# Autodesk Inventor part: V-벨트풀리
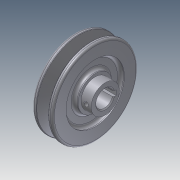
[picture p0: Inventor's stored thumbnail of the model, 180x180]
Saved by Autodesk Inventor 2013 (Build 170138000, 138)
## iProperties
Company: 한국ATC센터
Created: 2014-07
Part Number: V-벨트풀리
Document SubType Name: Modeling
Designer: KYOUNG IL JANG
Density: 7.86 g/cm^3
Material: 강, 연강
Mass: 593.01 g
Surface Area: 234.121 cm^2
Volume: 75.4466 cm^3
Author: KYOUNG IL JANG
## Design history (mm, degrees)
sketch "스케치1"
  geometry: L1 (-15, 0)-(15, 0); L2 (-15, 0)-(-15, 17); L3 (-15, 17)-(-11, 17); L4 (-11, 17)-(-11, 29); L5 (-11, 29)-(-15, 29); L6 (-15, 29)-(-15, 42.5); L7 (-15, 42.5)-(-10.976, 42.5); L8 (-10.976, 42.5)-(-7.154, 30); L9 (-7.154, 30)-(-2.846, 30); L10 (-2.846, 30)-(0.976, 42.5); L11 (0.976, 42.5)-(5, 42.5); L12 (5, 42.5)-(5, 29); L13 (5, 29)-(1, 29); L14 (1, 29)-(1, 17); L15 (1, 17)-(5, 17); L16 (5, 17)-(5, 14); L17 (5, 14)-(15, 14); L18 (15, 14)-(15, 0); L19 (-9.6, 38)-(-0.4, 38); 2 further points
  constraints: 38 end point, 11 parallel, 7 collinear, 3 equal length, 3 perpendicular, 2 point on line, 1 coincident, 1 horizontal, 1 midpoint
  dimensions: "d0" = 30 distance of L1.start L1.end; "d1" = 4.5 distance between parallel lines of L7 L19; "d2" = 8 distance between parallel lines of L9 L19; "d3" = 9.2 distance of L19.start L19.end; "d4" = 34 deg angle of L10 L8; "d5" = 20 distance between parallel lines of L12 L6; "d6" = 76 diameter of L19 L1; "d7" = 4 distance of L2.end L3.end; "d8" = 34 diameter of L3 L1; "d9" = 58 diameter of L5 L1; "d10" = 28 diameter of L17 L1
revolve "회전1" sketch "스케치1" stored, may be unused: angle "d11" = 90 deg
sketch "스케치2"
  geometry: L1 (-2.5, 8.124)-(-2.5, 10.8); L2 (-2.5, 10.8)-(2.5, 10.8); L3 (2.5, 10.8)-(2.5, 8.124); A1 r 8.5 centre (0, 0) between (-2.5, 8.124) and (2.5, 8.124); 1 further point
  constraints: 6 end point, 2 parallel, 2 point on circle, 1 centre point, 1 coincident, 1 horizontal, 1 vertical
  dimensions: "d12" = 17 diameter of A1; "d13" = 5 distance of L1.end L2.end; "d14" = 19.3 dimension on A1 L2 (computed from d12)
extrude "돌출1" cut sketch "스케치2" stored distance "d15" = 10; taper "d16" = 0 deg
chamfer "모따기1" distance "d17" = 1; stored, may be unused: second distance "d18" = 2, angle "d19" = 45 deg
node "작업 평면1"
sketch "스케치3"
  geometry: L1 (5, -14)-(5, 14) reference; 3 further points
  constraints: 1 horizontal alignment, 1 midpoint
  dimensions: "d20" = 5 distance from line of L1 point (0, 0)
hole "구멍1" sketch "스케치3" at (0, 0) diameter "d21" = 3.242; stored, may be unused: countersink angle "d25" = 90 deg, drill point angle "d27" = 118 deg; dims "d22" = 6, "d23" = 4, "d24" = 2, "d26" = 8
fillet "모깎기1" dims "d28" = 3, "d29" = 2, "d30" = 0.5, "d31" = 1
node "솔리드1"
